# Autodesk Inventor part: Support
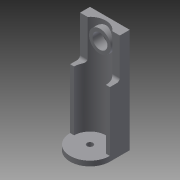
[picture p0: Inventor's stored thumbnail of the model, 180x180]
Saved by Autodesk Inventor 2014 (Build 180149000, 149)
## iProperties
Created: 2006-03
Part Number: Support
Document SubType Name: Modeling
Designer: debonom
Manufacturer: Standard
Standards Organization: Custom
Mass: 42.849 g
Surface Area: 163.994 cm^2
Volume: 42.849 cm^3
Density: 1 g/cm^3
Material: Generic
Appearance: Default
Author: debonom
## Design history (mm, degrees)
sketch "Sketch4"
  geometry: L1 (0, -28)-(0, 28) reference; L2 (-28, 0)-(28, 0) reference; L3 (20, 0)-(20, -20); L4 (20, -20)-(-20, -20); L5 (-20, -20)-(-20, 0); C1 r 3 at (0, 0); A1 r 20 centre (0, 0) between (20, 0) and (-20, 0); 1 further point
  constraints: 6 end point, 2 centre point, 2 coincident, 2 perpendicular, 2 point on circle, 2 tangent, 1 parallel, 1 point on line
  dimensions: "d7" = 20 radius of A1; "d8" = 20 distance of L3.start L3.end; "d9" = 6 diameter of C1
extrude "Extrusion3" new body sketch "Sketch4" distance "d10" = 5; taper "d11" = 0 deg
sketch "Sketch5"
  geometry: L1 (0, 28)-(0, -28) reference; L2 (28, 0)-(-28, 0) reference; L3 (-16, 0)-(-20, 0); L4 (-20, 0)-(-20, 20); L5 (-20, 20)-(20, 20); L6 (20, 20)-(20, 0); A1 r 16 centre (0, 0) between (16, 0) and (-16, 0); 1 further point
  constraints: 8 end point, 2 perpendicular, 2 point on circle, 2 point on line, 1 centre point, 1 coincident, 1 collinear, 1 parallel
  dimensions: "d14" = 16 radius of A1
extrude "Extrusion4" join sketch "Sketch5" distance "d12" = 100; taper "d13" = 0 deg
feature "Sculpt1"
  workplane "Work Plane1"
  workplane "Work Plane2"
sketch "Sketch6"
  geometry: L1 (-12.49, 21)-(-12.49, -126) reference; L2 (0, 0)-(-24.98, 0) reference; C1 r 11 at (-12.49, -15); 1 further point
  constraints: 1 centre point, 1 point on line
  dimensions: "d17" = 15 distance from line of L2 C1.centre; "d18" = 22 diameter of C1
extrude "Extrusion5" join sketch "Sketch6" stored distance "d19" = 50; taper "d20" = 0 deg
sketch "Sketch7"
  geometry: C1 r 11 at (0, 0) reference; C2 r 7.5 at (0, 0); 1 further point
  constraints: 1 centre point, 1 coincident
  dimensions: "d21" = 15 diameter of C2
extrude "Extrusion6" cut sketch "Sketch7" distance "d22" = 50; taper "d23" = 0 deg
fillet "Fillet1" dims "d24" = 3
body "Solid1"
